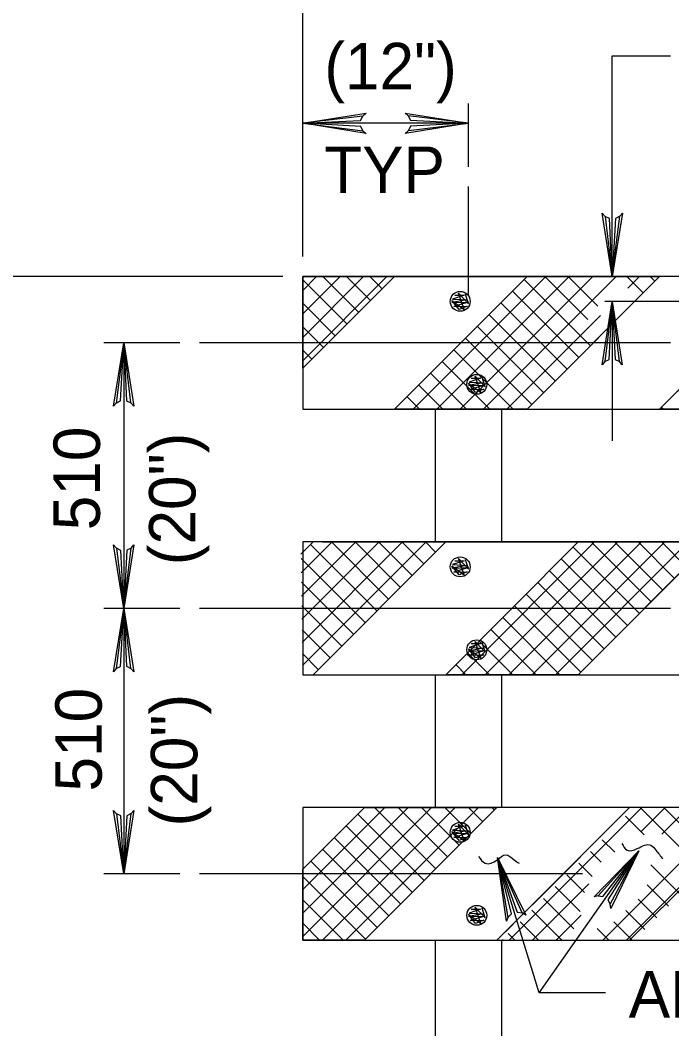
# Model space of a CAD drawing. Extents: x -4 to 901, y -468 to 720.
# Drawn here: x 91.5 to 138.7, y -24.2 to 48.7 of the extents above; entities that cross this region are included whole.
import ezdxf

# ---------------------------------------------------------------- set-up
doc = ezdxf.new("R2010")
doc.units = 0
doc.layers.add('2', color=7, linetype='Continuous')
doc.layers.add('3', color=7, linetype='Continuous')

msp = doc.modelspace()

# ---------------------------------------------------------------- linework, layer by layer
at = {"layer": '2'}
for p, q in [((111.99775, 31.603875), (111.99775, 66.373875)), ((134.40175, 30.163875), (134.40175, 46.117875)), ((123.99775, 38.101875), (123.99775, 42.681875)), ((123.99775, 41.241875), (111.99775, 41.241875)), ((123.99775, 28.781875), (123.99775, 36.661875)), ((110.55775, 30.163875), (65.93175, 30.163875)), ((111.99775, 23.529875), (118.63175, 30.163875)), ((113.67775, 30.163875), (136.08175, 30.163875)), ((118.63175, 20.563875), (128.23175, 30.163875)), ((135.4125, 27.744625), (137.83175, 30.163875)), ((137.83175, 20.563875), (147.43175, 30.163875)), ((123.86575, 28.471875), (122.79975, 28.269875)), ((123.67775, 28.809875), (122.84975, 28.527875)), ((122.84975, 28.527875), (123.86575, 28.471875)), ((123.00175, 28.809875), (123.67775, 28.809875)), ((123.69375, 27.779875), (123.28175, 28.959875)), ((123.28175, 28.959875), (124.00175, 28.189875)), ((124.00175, 28.189875), (123.78575, 28.887875)), ((123.31175, 27.779875), (122.79975, 28.435875)), ((122.79975, 28.435875), (123.69375, 27.779875)), ((122.79975, 28.269875), (123.98775, 28.311875)), ((123.98775, 28.311875), (122.92975, 27.987875)), ((122.92975, 27.987875), (123.90975, 28.009875)), ((123.90975, 28.009875), (123.31175, 27.779875)), ((123.39775, 28.363875), (123.39775, 28.363875)), ((146.37975, 28.363875), (133.87525, 28.363875)), ((128.23175, 20.563875), (133.429, 25.761125)), ((103.09975, 25.363875), (97.60175, 25.363875)), ((99.04175, 25.363875), (99.04175, 6.163875)), ((138.62775, 25.363875), (104.53975, 25.363875)), ((124.87775, 22.809875), (124.04975, 22.527875)), ((124.20175, 22.809875), (124.87775, 22.809875)), ((124.89375, 21.779875), (124.48175, 22.959875)), ((124.48175, 22.959875), (125.20175, 22.189875)), ((125.20175, 22.189875), (124.98575, 22.887875)), ((125.06575, 22.471875), (123.99975, 22.269875)), ((124.51175, 21.779875), (123.99975, 22.435875)), ((123.99975, 22.435875), (124.89375, 21.779875)), ((123.99975, 22.269875), (125.18775, 22.311875)), ((124.04975, 22.527875), (125.06575, 22.471875)), ((125.18775, 22.311875), (124.12975, 21.987875)), ((124.12975, 21.987875), (125.10975, 22.009875)), ((125.10975, 22.009875), (124.51175, 21.779875)), ((124.59775, 22.363875), (124.59775, 22.363875)), ((111.87375, 10.091875), (112.74575, 10.963875)), ((111.99775, 10.963875), (111.99775, 1.363875)), ((243.5185, 10.963875), (111.99775, 10.963875)), ((112.74575, 1.363875), (122.34575, 10.963875)), ((112.74575, 1.363875), (122.34575, 10.963875)), ((113.43775, 10.963875), (164.43975, 10.963875)), ((113.43775, 10.963875), (164.43975, 10.963875)), ((122.34575, 1.363875), (131.94575, 10.963875)), ((122.34575, 1.363875), (131.94575, 10.963875)), ((131.94575, 1.363875), (141.54575, 10.963875)), ((131.94575, 1.363875), (141.54575, 10.963875)), ((123.67775, 9.609875), (122.84975, 9.327875)), ((123.00175, 9.609875), (123.67775, 9.609875)), ((123.69375, 8.579875), (123.28175, 9.759875)), ((123.28175, 9.759875), (124.00175, 8.989875)), ((124.00175, 8.989875), (123.78575, 9.687875)), ((123.86575, 9.271875), (122.79975, 9.069875)), ((123.31175, 8.579875), (122.79975, 9.235875)), ((122.79975, 9.235875), (123.69375, 8.579875)), ((122.79975, 9.069875), (123.98775, 9.111875)), ((122.84975, 9.327875), (123.86575, 9.271875)), ((123.98775, 9.111875), (122.92975, 8.787875)), ((122.92975, 8.787875), (123.90975, 8.809875)), ((123.90975, 8.809875), (123.31175, 8.579875)), ((123.39775, 9.163875), (123.39775, 9.163875)), ((103.09975, 6.163875), (97.60175, 6.163875)), ((99.04175, 6.163875), (99.04175, -13.036125)), ((138.62775, 6.163875), (104.53975, 6.163875)), ((124.89375, 2.579875), (124.48175, 3.759875)), ((124.48175, 3.759875), (125.20175, 2.989875)), ((125.20175, 2.989875), (124.98575, 3.687875)), ((125.06575, 3.271875), (123.99975, 3.069875)), ((124.51175, 2.579875), (123.99975, 3.235875)), ((123.99975, 3.235875), (124.89375, 2.579875)), ((123.99975, 3.069875), (125.18775, 3.111875)), ((124.87775, 3.609875), (124.04975, 3.327875)), ((124.04975, 3.327875), (125.06575, 3.271875)), ((125.18775, 3.111875), (124.12975, 2.787875)), ((124.20175, 3.609875), (124.87775, 3.609875)), ((124.59775, 3.163875), (124.59775, 3.163875)), ((124.12975, 2.787875), (125.10975, 2.809875)), ((125.10975, 2.809875), (124.51175, 2.579875)), ((111.99775, 1.363875), (243.5185, 1.363875)), ((111.99775, -12.698125), (116.45975, -8.236125)), ((111.99775, -12.698125), (116.45975, -8.236125)), ((111.99775, -8.236125), (111.99775, -17.836125)), ((243.5185, -8.236125), (111.99775, -8.236125)), ((116.45975, -17.836125), (126.05975, -8.236125)), ((116.45975, -17.836125), (126.05975, -8.236125)), ((126.05975, -17.836125), (135.65975, -8.236125)), ((128.62425, -15.271625), (135.65975, -8.236125)), ((135.65975, -17.836125), (145.25975, -8.236125)), ((135.65975, -17.836125), (145.25975, -8.236125)), ((123.69375, -10.620125), (123.28175, -9.440125)), ((123.28175, -9.440125), (124.00175, -10.210125)), ((124.89975, -9.396125), (124.89975, -9.396125)), ((125.28775, -9.010125), (125.28775, -9.010125)), ((123.86575, -9.928125), (122.79975, -10.130125)), ((123.31175, -10.620125), (122.79975, -9.964125)), ((122.79975, -9.964125), (123.69375, -10.620125)), ((122.79975, -10.130125), (123.98775, -10.088125)), ((123.67775, -9.590125), (122.84975, -9.872125)), ((122.84975, -9.872125), (123.86575, -9.928125)), ((123.98775, -10.088125), (122.92975, -10.412125)), ((123.00175, -9.590125), (123.67775, -9.590125)), ((123.39775, -10.036125), (123.39775, -10.036125)), ((124.00175, -10.210125), (123.78575, -9.512125)), ((123.99775, -10.036125), (123.99775, -10.036125)), ((124.12775, -10.168125), (124.12775, -10.168125)), ((124.51375, -9.782125), (124.51375, -9.782125)), ((122.92975, -10.412125), (123.90975, -10.390125)), ((123.90975, -10.390125), (123.31175, -10.620125)), ((103.09975, -13.036125), (97.60175, -13.036125)), ((132.24425, -13.036125), (104.53975, -13.036125)), ((123.99775, -16.036125), (123.99775, -16.036125)), ((125.06575, -15.928125), (123.99975, -16.130125)), ((124.51175, -16.620125), (123.99975, -15.964125)), ((123.99975, -15.964125), (124.89375, -16.620125)), ((124.87775, -15.590125), (124.04975, -15.872125)), ((124.04975, -15.872125), (125.06575, -15.928125)), ((124.20175, -15.590125), (124.87775, -15.590125)), ((124.89375, -16.620125), (124.48175, -15.440125)), ((124.48175, -15.440125), (125.20175, -16.210125)), ((124.59775, -16.036125), (124.59775, -16.036125)), ((125.20175, -16.210125), (124.98575, -15.512125)), ((123.99975, -16.130125), (125.18775, -16.088125)), ((125.18775, -16.088125), (124.12975, -16.412125)), ((124.12975, -16.412125), (125.10975, -16.390125)), ((125.10975, -16.390125), (124.51175, -16.620125)), ((126.05975, -17.836125), (127.2195, -16.676375)), ((111.99775, -17.836125), (243.5185, -17.836125))]:
    msp.add_line(p, q, dxfattribs=at)
for points in [[(134.40175, 46.117875), (138.6165, 46.117875)], [(116.35775, 40.695875), (116.19375, 41.011875), (111.99775, 41.241875), (116.35775, 40.695875), (116.57975, 40.503875), (111.99775, 41.241875), (116.19175, 41.449875), (116.34375, 41.761875), (111.99775, 41.241875), (116.57975, 41.971875), (116.34375, 41.761875)], [(119.63775, 41.789875), (119.80175, 41.473875), (123.99775, 41.241875), (119.63775, 41.789875), (119.41575, 41.981875), (123.99775, 41.241875), (119.80375, 41.035875), (119.65175, 40.723875), (123.99775, 41.241875), (119.41575, 40.513875), (119.65175, 40.723875)], [(134.94775, 34.521875), (134.63375, 34.359875), (134.40175, 30.163875), (134.94775, 34.521875), (135.13975, 34.745875), (134.40175, 30.163875), (134.19375, 34.355875), (133.88175, 34.509875), (134.40175, 30.163875), (133.67375, 34.745875), (133.88175, 34.509875)], [(111.99775, 24.063875), (118.09575, 30.163875)], [(111.99775, 25.761875), (116.39975, 30.163875)], [(111.99775, 27.457875), (114.70175, 30.163875)], [(111.99775, 29.155875), (113.00575, 30.163875)], [(170.943, 30.163875), (111.99775, 30.163875), (111.99775, 20.563875), (244.7635, 20.563875)], [(115.19575, 26.727875), (111.99775, 29.925875)], [(116.04375, 27.575875), (113.45775, 30.163875)], [(116.89375, 28.423875), (115.15575, 30.161875)], [(117.74175, 29.273875), (116.85175, 30.163875)], [(118.58975, 30.121875), (118.54975, 30.163875)], [(119.99575, 20.563875), (129.59575, 30.161875)], [(121.69375, 20.563875), (131.29375, 30.163875)], [(123.38975, 20.563875), (132.98975, 30.163875)], [(125.08775, 20.563875), (134.68775, 30.163875)], [(132.82375, 25.155875), (128.02375, 29.955875)], [(132.6365, 27.043125), (129.51575, 30.163875)], [(133.3555, 28.020125), (131.21175, 30.163875)], [(136.64375, 28.973875), (135.45575, 30.163875)], [(135.527, 29.307125), (136.38375, 30.163875)], [(137.49175, 29.823875), (137.15175, 30.163875)], [(131.97575, 24.307875), (127.17575, 29.107875)], [(114.34775, 25.879875), (111.99775, 28.229875)], [(131.12775, 23.459875), (126.32775, 28.259875)], [(133.85375, 24.003875), (134.16975, 24.165875), (134.40175, 28.363875), (133.85375, 24.003875), (133.66375, 23.779875), (134.40175, 28.363875), (134.60775, 24.169875), (134.92175, 24.015875), (134.40175, 28.363875), (135.12975, 23.779875), (134.92175, 24.015875)], [(134.40175, 28.363875), (134.40175, 18.283875)], [(130.27975, 22.609875), (125.47975, 27.409875)], [(126.78375, 20.563875), (133.5595, 27.339625)], [(113.49975, 25.029875), (111.99775, 26.531875)], [(129.42975, 21.761875), (124.62975, 26.561875)], [(128.58175, 20.913875), (123.78175, 25.713875)], [(98.49575, 21.003875), (98.81175, 21.165875), (99.04175, 25.363875), (98.49575, 21.003875), (98.30375, 20.779875), (99.04175, 25.363875), (99.24975, 21.169875), (99.56175, 21.015875), (99.04175, 25.363875), (99.77175, 20.779875), (99.56175, 21.015875)], [(112.64975, 24.181875), (111.99775, 24.835875)], [(127.23575, 20.563875), (122.93375, 24.865875)], [(125.53775, 20.563875), (122.08575, 24.015875)], [(123.84175, 20.563875), (121.23575, 23.167875)], [(122.14375, 20.563875), (120.38775, 22.319875)], [(120.44775, 20.563875), (119.53975, 21.471875)], [(118.74975, 20.563875), (118.69175, 20.621875)], [(121.59775, 10.963875), (121.59775, 20.563875), (126.39775, 20.563875), (126.39775, 10.963875)], [(138.07575, 20.563875), (137.95375, 20.685875)], [(111.89375, 8.721875), (114.13575, 10.963875)], [(111.91775, 7.047875), (115.83175, 10.963875)], [(111.94175, 5.373875), (117.52975, 10.963875)], [(111.96375, 3.701875), (119.22575, 10.963875)], [(111.98775, 2.027875), (120.92375, 10.963875)], [(118.21575, 6.833875), (114.08775, 10.963875)], [(119.06375, 7.681875), (115.78375, 10.963875)], [(119.91375, 8.529875), (117.48175, 10.963875)], [(120.76175, 9.379875), (119.17775, 10.963875)], [(121.60975, 10.227875), (120.87575, 10.963875)], [(123.51375, 1.363875), (133.11375, 10.963875)], [(125.21175, 1.363875), (134.81175, 10.963875)], [(126.90775, 1.363875), (136.50775, 10.963875)], [(128.60575, 1.363875), (138.20575, 10.963875)], [(130.30375, 1.363875), (139.90175, 10.963875)], [(137.21175, 6.629875), (132.87775, 10.963875)], [(138.05975, 7.477875), (134.57575, 10.963875)], [(138.90975, 8.325875), (136.27175, 10.961875)], [(139.75775, 9.175875), (137.96975, 10.963875)], [(99.58975, 10.521875), (99.27375, 10.359875), (99.04175, 6.163875), (99.58975, 10.521875), (99.78175, 10.745875), (99.04175, 6.163875), (98.83575, 10.355875), (98.52375, 10.509875), (99.04175, 6.163875), (98.31375, 10.745875), (98.52375, 10.509875)], [(117.36775, 5.985875), (112.56775, 10.785875), (112.56775, 10.785875)], [(136.36375, 5.779875), (131.56375, 10.579875)], [(116.51975, 5.135875), (111.87775, 9.777875)], [(135.51375, 4.931875), (130.71375, 9.731875)], [(134.66575, 4.083875), (129.86575, 8.883875)], [(115.66975, 4.287875), (111.90375, 8.055875)], [(133.81775, 3.235875), (129.01775, 8.035875)], [(132.96975, 2.385875), (128.16975, 7.185875)], [(98.49575, 1.803875), (98.81175, 1.965875), (99.04175, 6.163875), (98.49575, 1.803875), (98.30375, 1.579875), (99.04175, 6.163875), (99.24975, 1.969875), (99.56175, 1.815875), (99.04175, 6.163875), (99.77175, 1.579875), (99.56175, 1.815875)], [(114.82175, 3.439875), (111.92775, 6.333875)], [(132.11975, 1.537875), (127.31975, 6.337875)], [(130.59975, 1.363875), (126.47175, 5.489875)], [(113.97375, 2.591875), (111.95175, 4.611875)], [(128.90175, 1.363875), (125.62375, 4.641875)], [(127.20375, 1.363875), (124.77575, 3.791875)], [(125.50775, 1.363875), (123.92575, 2.943875)], [(113.12375, 1.741875), (111.97575, 2.891875)], [(123.80975, 1.363875), (123.07775, 2.095875)], [(121.59775, -8.236125), (121.59775, 1.363875)], [(126.39775, 1.363875), (126.39775, -8.236125)], [(99.58975, -8.678125), (99.27375, -8.840125), (99.04175, -13.036125), (99.58975, -8.678125), (99.78175, -8.454125), (99.04175, -13.036125), (98.83575, -8.844125), (98.52375, -8.690125), (99.04175, -13.036125), (98.31375, -8.454125), (98.52375, -8.690125)], [(111.99775, -17.570125), (121.32975, -8.236125)], [(111.99775, -15.872125), (119.63375, -8.236125)], [(111.99775, -14.176125), (117.93575, -8.236125)], [(113.42775, -17.836125), (123.02775, -8.236125)], [(115.12575, -17.836125), (124.72375, -8.236125)], [(120.77975, -13.516125), (115.97975, -8.716125)], [(121.62975, -12.668125), (117.19775, -8.236125)], [(122.47775, -11.818125), (118.89575, -8.236125)], [(123.32575, -10.970125), (120.59175, -8.236125)], [(124.17375, -10.122125), (122.28975, -8.236125)], [(125.02375, -9.274125), (123.98775, -8.236125)], [(125.87175, -8.424125), (125.68375, -8.236125)], [(126.93775, -17.836125), (136.53775, -8.236125)], [(133.72575, -17.836125), (143.32575, -8.236125)], [(135.42375, -17.836125), (145.02375, -8.236125)], [(141.01375, -12.820125), (136.42975, -8.236125)], [(136.48975, -9.982125), (138.23575, -8.236125)], [(137.99225, -10.175625), (139.93175, -8.236125)], [(141.86175, -11.972125), (138.12775, -8.236125)], [(136.71525, -10.219625), (135.36575, -8.870125)], [(119.93175, -14.364125), (115.13175, -9.564125)], [(119.08375, -15.214125), (114.28375, -10.414125)], [(134.58275, -11.481125), (133.66775, -10.566125)], [(118.23375, -16.062125), (113.43375, -11.262125)], [(129.10975, -21.636125), (136.33175, -11.368125)], [(133.58775, -12.184125), (132.81975, -11.416125)], [(133.37775, -14.618125), (133.72775, -14.668125), (136.33175, -11.368125), (133.37775, -14.618125), (133.09175, -14.692125), (136.33175, -11.368125), (134.08975, -14.916125), (134.25775, -15.222125), (136.33175, -11.368125), (134.29175, -15.536125), (134.25775, -15.222125)], [(117.38575, -16.910125), (112.58575, -12.110125)], [(133.90975, -21.636125), (129.10975, -21.636125), (126.09175, -11.862125)], [(126.85375, -16.188125), (127.10775, -15.940125), (126.09175, -11.862125), (126.85375, -16.188125), (126.73775, -16.458125), (126.09175, -11.862125), (127.52575, -15.808125), (127.86975, -15.862125), (126.09175, -11.862125), (128.13975, -16.026125), (127.86975, -15.862125)], [(132.9475, -13.239875), (131.97175, -12.264125)], [(139.31775, -14.518125), (137.1895, -12.389875)], [(132.386, -14.375875), (131.12175, -13.112125)], [(116.53775, -17.758125), (111.99775, -13.218125)], [(128.63575, -17.836125), (132.706, -13.765875)], [(138.46775, -15.366125), (136.92725, -13.825625)], [(132.07575, -15.762125), (130.27375, -13.960125)], [(114.91975, -17.836125), (111.99775, -14.916125)], [(131.6305, -17.013375), (129.42575, -14.810125)], [(137.61975, -16.216125), (136.27, -14.866375)], [(130.75575, -17.836125), (128.57775, -15.658125)], [(130.33175, -17.836125), (132.154, -16.013875)], [(136.77175, -17.064125), (135.39, -15.682375)], [(113.22175, -17.836125), (111.99775, -16.612125)], [(129.05975, -17.836125), (127.72775, -16.506125)], [(135.84775, -17.836125), (134.51, -16.498625)], [(127.36175, -17.836125), (126.87975, -17.354125)], [(134.14975, -17.836125), (133.301, -16.987375)], [(121.59775, -42.262125), (121.59775, -17.836125)], [(126.39775, -17.836125), (126.39775, -41.332125)], [(126.51375, -17.836125), (126.45575, -17.780125)]]:
    msp.add_lwpolyline(points, dxfattribs=at)
for points in [[(111.99775, 23.529875), (111.99775, 30.163875), (118.63175, 30.163875)], [(118.63175, 20.563875), (128.23175, 30.163875), (137.83175, 30.163875), (128.23175, 20.563875)], [(137.83175, 20.563875), (147.43175, 30.163875), (157.03175, 30.163875), (147.43175, 20.563875)], [(122.34575, 1.363875), (131.94575, 10.963875), (141.54575, 10.963875), (131.94575, 1.363875)], [(111.99775, -12.698125), (116.45975, -8.236125), (126.05975, -8.236125), (116.45975, -17.836125), (111.99775, -17.836125)]]:
    msp.add_lwpolyline(points, close=True, dxfattribs=at)
for centre in [(123.39789, 28.362972), (124.59789, 22.362972), (123.39789, 9.162972), (124.59789, 3.162972), (123.39789, -10.037028), (124.59789, -16.037028)]:
    msp.add_circle(centre, 0.72, dxfattribs=at)
for points in [[(135.10525, -10.839375), (135.47525, -11.331375), (136.21125, -11.207375), (137.19525, -10.961375), (137.56525, -11.331375), (138.05725, -11.945375)], [(124.71975, -11.784125), (125.21175, -12.276125), (126.07175, -12.030125), (126.68575, -11.660125), (127.30175, -12.030125), (127.66975, -12.276125)]]:
    msp.add_spline(points, degree=3, dxfattribs=at)

# ---------------------------------------------------------------- texts
at = {"layer": '3'}
for s, height, p in [('(12")', 3.36, (113.56275, 43.698375)), ('TYP', 3.36, (113.55325, 36.201875)), ('ALTERNATE RED AND WHITE', 3.359988, (135.59175, -23.430125))]:
    msp.add_text(s, height=height, dxfattribs=at).set_placement(p)
for s, p in [('510', (97.32075, 11.807625)), ('(20")', (104.23675, 9.281625)), ('510', (97.45125, -7.083625)), ('(20")', (104.36725, -9.609625))]:
    msp.add_text(s, height=3.36, rotation=90, dxfattribs=at).set_placement(p)

doc.saveas('drawing.dxf')
